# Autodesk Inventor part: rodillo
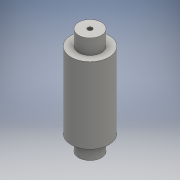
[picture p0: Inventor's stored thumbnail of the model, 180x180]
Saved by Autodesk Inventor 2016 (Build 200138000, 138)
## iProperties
Created: 2016-06
Part Number: rodillo
Material: Generic
Document SubType Name: Modeling
Designer: yesi alvarez
Mass: 27.9366 g
Surface Area: 60.3971 cm^2
Volume: 27.9366 cm^3
Density: 1 g/cm^3
Appearance: Default
Author: yesi alvarez
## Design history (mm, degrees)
sketch "Sketch1"
  geometry: C1 r 12.5 at (0, 0); 1 further point
  constraints: 1 centre point, 1 coincident
  dimensions: "d0" = 25 diameter of C1
extrude "Extrusion1" new body sketch "Sketch1" distance "d1" = 25; taper "d2" = 0 deg
sketch "Sketch2"
  geometry: C1 r 7.5 at (0, 0); 1 further point
  constraints: 1 centre point, 1 coincident
  dimensions: "d3" = 15 diameter of C1
extrude "Extrusion2" join sketch "Sketch2" distance "d4" = 10; taper "d5" = 0 deg
sketch "Sketch3"
  geometry: C1 r 1.5 at (0, 0); 1 further point
  constraints: 1 centre point, 1 coincident
  dimensions: "d6" = 3 diameter of C1
extrude "Extrusion3" cut sketch "Sketch3" distance "d7" = 10; taper "d8" = 0 deg
thread "Thread1" dims "d9" = 10, "d10" = 0
mirror "Mirror1"
body "Solid1"
